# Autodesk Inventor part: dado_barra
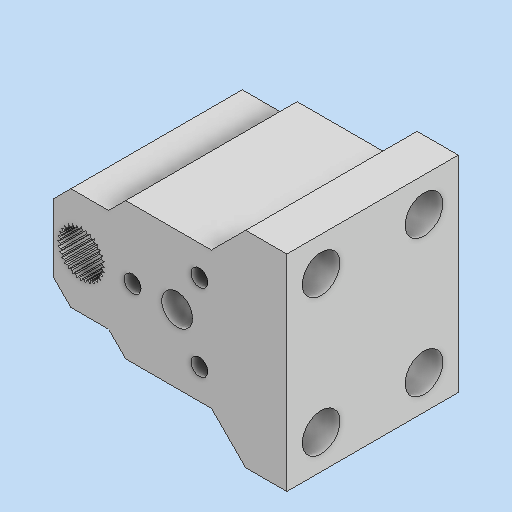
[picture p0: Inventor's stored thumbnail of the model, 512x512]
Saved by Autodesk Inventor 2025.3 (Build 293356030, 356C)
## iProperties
Created: 2025-12
Part Number: dado_barra
Material: Generico
Document SubType Name: Modeling
Designer: Ryzen5700u
Density: 1 g/cm^3
Appearance: Default
Author: Ryzen5700u
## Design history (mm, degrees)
sketch "Schizzo1"
  geometry: L1 (-10, 10)-(10, 10); L2 (10, 10)-(10, -10); L3 (10, -10)-(-10, -10); L4 (-10, -10)-(-10, 10); L5 (-10, 10)-(10, -10); L6 (10, 10)-(-10, -10); L7 (-10, 7.5)-(-18, 7.5); L8 (-18, 7.5)-(-18, -7.5); L9 (-18, -7.5)-(-10, -7.5); L10 (-10, -7.5)-(-10, 7.5); L11 (0, 0)-(-22.766, 0); C1 r 1.621 at (-14, 0) reference; C2 r 3.05 at (-14, 0); C3 r 1.23 at (3.25, 5.629) reference; C4 r 1.23 at (3.25, -5.629) reference; C5 r 1.23 at (-6.5, 0) reference; C6 r 2.25 at (0, 0); 1 further point
  constraints: 22 end point, 4 parallel, 3 horizontal, 2 centre point, 2 coincident, 2 midpoint, 2 perpendicular, 1 point on line, 1 other
  dimensions: "d0" = 20 distance of L2.end L3.end; "d1" = 20 distance of L1.end L2.end; "d2" = 8 distance of L9.end L8.end; "d3" = 15 distance of L8.end L7.end; "d4" = 6.1 diameter of C2; "d7" = 4.5 diameter of C6
extrude "Estrusione1" new body sketch "Schizzo1" distance "d5" = 25; taper "d6" = 0 deg
sketch "Schizzo2"
  geometry: L1 (-14, 0)-(-6.5, 0); L2 (-14, 0.2)-(-6.5, 0.2); L3 (-14, -0.2)-(-6.5, -0.2); L4 (-10.957, -0.2)-(-10.592, 0); L5 (-10.957, 0.2)-(-10.592, 0); C1 r 1.23 at (-6.5, 0) reference; A1 r 3.05 centre (-14, 0) between (-10.957, -0.2) and (-10.957, 0.2) reference; 1 further point
  constraints: 10 end point, 3 point on line, 2 parallel, 2 point on circle, 1 horizontal
  dimensions: "d9" = 0.2 distance between parallel lines of L1 L2; "d10" = 0.2 distance between parallel lines of L1 L3
extrude "Estrusione2" cut sketch "Schizzo2" extent not by distance; stored distance "d11" = 0; taper "d12" = 0 deg
chamfer "Smusso1" distance "d16" = 2.5; stored, may be unused: second distance "d17" = 2, angle "d18" = 45 deg
sketch "Schizzo3"
  geometry: L1 (0, 0)-(0, 20) reference; L2 (0, 20)-(-25, 20) reference; L3 (-25, 0)-(-25, 20) reference; L4 (0, 0)-(-25, 0) reference; L5 (-25, 25)-(0, 25); L6 (0, 25)-(0, -5); L7 (0, -5)-(-25, -5); L8 (-25, -5)-(-25, 25); L9 (-25, 10)-(0, 10) reference; L10 (-25, 25)-(0, -5); L11 (0, 25)-(-25, -5); 5 further points
  constraints: 12 end point, 3 midpoint, 2 parallel, 1 horizontal, 1 perpendicular
  dimensions: "d30" = 30 distance of L5.end L6.end
extrude "Estrusione3" join sketch "Schizzo3" distance "d19" = 6; taper "d20" = 0 deg
sketch "Schizzo4"
  geometry: L1 (-25, 20)-(0, 20) reference; L2 (-25, 0)-(-25, 2.5) reference; L3 (0, 20)-(-25, 0); L4 (0, 0)-(-25, 0) reference; L5 (-25, 0)-(0, 0); L6 (0, 0)-(-25, 20); L7 (-20, 20)-(-5, 20); L8 (-5, 20)-(-5, 0); L9 (-5, 0)-(-20, 0); L10 (-20, 0)-(-20, 20); L11 (-20, 20)-(-5, 0); L12 (-5, 20)-(-20, 0); 3 further points
  constraints: 18 end point, 3 equal length, 3 midpoint, 1 horizontal, 1 perpendicular
  dimensions: "d21" = 15 distance of L8.end L9.end; "d22" = 20 distance of L7.end L8.end
hole "Foro1" sketch "Schizzo4" at (-5, 0), (-5, 20), (-20, 0), (-20, 20) diameter "d23" = 5.5; stored, may be unused: countersink angle "d27" = 90 deg, drill point angle "d29" = 0 deg; dims "d24" = 6, "d25" = 4, "d26" = 2, "d28" = 5.5
chamfer "Smusso2" distance "d31" = 5; stored, may be unused: second distance "d32" = 2, angle "d33" = 45 deg
node "Solido1"
pattern_circular "Serie circolare1" dims angle "d14" = 360 deg
node "Riferimento1"
node "Riferimento2"
node "Riferimento3"
node "Riferimento4"
node "Linea chiusa proiettata1"
